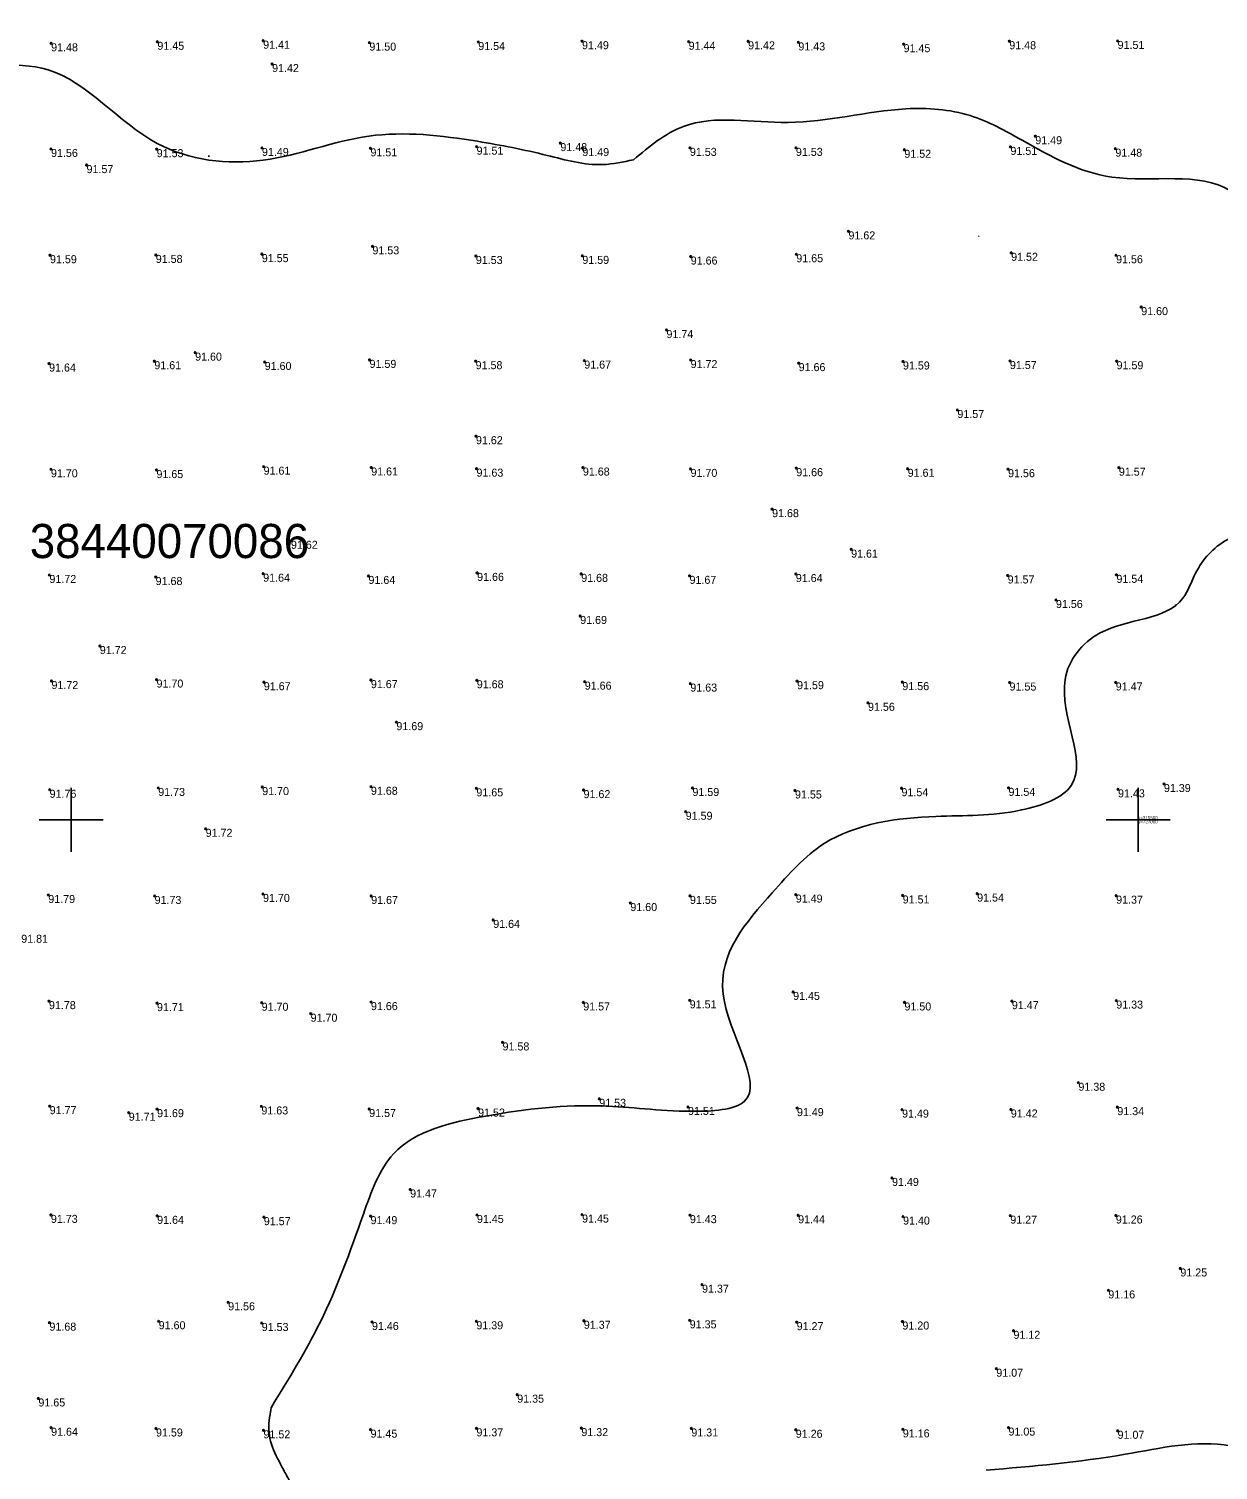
# Model space of a CAD drawing. Extents: x 316000 to 728450, y 314368 to 726000.
# Drawn here: x 726480 to 727038, y 315195 to 315871 of the extents above; entities that cross this region are included whole.
import ezdxf

# ---------------------------------------------------------------- set-up
doc = ezdxf.new("R2010")
doc.units = 0
for name, color, linetype in [('59', 7, 'Continuous'), ('GEOD_ELEM_####_####_#', 7, 'Continuous'), ('GEOD_KORD_####_TKST_#', 7, 'Continuous'), ('RELJ_AATZ_####_TKST_#', 7, 'Continuous'), ('RELJ_ELEM_####_####_#', 7, 'Continuous'), ('RELJ_HORZ_PAMT_####_#', 7, 'Continuous')]:
    doc.layers.add(name, color=color, linetype=linetype)

msp = doc.modelspace()

# ---------------------------------------------------------------- linework, layer by layer
at = {"layer": 'GEOD_ELEM_####_####_#'}
for p, q in [((726500, 315515), (726500, 315500)), ((727000, 315515), (727000, 315500)), ((726485, 315500), (726500, 315500)), ((726500, 315500), (726500, 315485)), ((726500, 315500), (726515, 315500)), ((726985, 315500), (727000, 315500)), ((727000, 315500), (727000, 315485)), ((727000, 315500), (727015, 315500))]:
    msp.add_line(p, q, dxfattribs=at)
at = {"layer": 'RELJ_ELEM_####_####_#'}
for centre in [(726490.67, 315863.76), (726540.47, 315864.48), (726590.02, 315864.97), (726639.81, 315864.09), (726690.82, 315864.36), (726739.45, 315864.76), (726789.42, 315864.5), (726817.28, 315864.7), (726840.82, 315864.18), (726890.11, 315863.35), (726939.66, 315864.74), (726990.41, 315864.88), (726594.22, 315854.05), (726951.84, 315820.25), (726490.64, 315814.28), (726540.15, 315814.17), (726589.46, 315814.74), (726640.3, 315814.55), (726690.03, 315815.34), (726729.3, 315817.01), (726739.58, 315814.68), (726789.99, 315814.78), (726839.67, 315814.78), (726890.48, 315813.88), (726940.2, 315815.25), (726989.37, 315814.41), (726507.27, 315806.7), (726864.29, 315775.65), (726490.15, 315764.49), (726539.71, 315764.63), (726589.39, 315765), (726641.23, 315768.66), (726689.69, 315764.12), (726739.59, 315764.18), (726839.86, 315764.94), (726940.52, 315765.61), (726989.7, 315764.47), (726790.38, 315763.86), (727001.47, 315740.16), (726779.01, 315729.41), (726558.15, 315718.83), (726489.72, 315713.73), (726539.04, 315714.82), (726590.75, 315714.48), (726639.88, 315715.45), (726689.59, 315714.84), (726740.5, 315715.11), (726790.33, 315715.36), (726840.95, 315713.92), (726889.82, 315714.69), (726939.94, 315714.9), (726989.92, 315714.82), (726915.34, 315691.97), (726689.75, 315679.69), (726490.57, 315664.17), (726540.03, 315663.82), (726590.23, 315665.42), (726640.66, 315665.03), (726690.01, 315664.48), (726739.85, 315665), (726790.29, 315664.37), (726839.82, 315664.71), (726892.05, 315664.43), (726939.09, 315664.24), (726991, 315664.94), (726828.52, 315645.51), (726603.04, 315630.7), (726865.58, 315626.64), (726690.29, 315615.66), (726489.87, 315614.68), (726539.64, 315613.7), (726590.04, 315615.27), (726639.37, 315614.23), (726739.06, 315615.19), (726789.81, 315614.27), (726839.63, 315615.11), (726938.9, 315614.44), (726989.86, 315614.74), (726961.52, 315602.95), (726738.59, 315595.48), (726513.48, 315581.38), (726490.83, 315564.98), (726540.07, 315565.67), (726590.33, 315564.43), (726640.51, 315565.41), (726690.13, 315565.35), (726740.72, 315564.7), (726790.2, 315563.79), (726840.23, 315564.92), (726889.54, 315564.48), (726939.78, 315564.28), (726989.54, 315564.32), (726873.46, 315554.78), (726652.46, 315545.72), (726540.86, 315514.9), (726589.58, 315515.3), (726640.53, 315515.45), (726689.94, 315514.7), (726791.18, 315514.87), (726889.15, 315514.77), (726939.27, 315514.94), (726990.6, 315514.22), (727012.11, 315516.73), (726489.95, 315514.04), (726740.16, 315513.88), (726839.23, 315513.71), (726788.03, 315503.74), (726563.09, 315495.75), (726489.34, 315464.73), (726539.15, 315464.29), (726589.97, 315465.25), (726640.64, 315464.28), (726762.08, 315460.96), (726790.02, 315464.32), (726839.61, 315464.94), (726889.7, 315464.53), (726924.6, 315465.4), (726989.73, 315464.41), (726697.83, 315453.07), (726489.65, 315415.01), (726540.27, 315414.08), (726589.32, 315414.26), (726640.54, 315414.56), (726740.01, 315414.39), (726789.91, 315415.38), (726838.36, 315419.33), (726890.53, 315414.39), (726940.85, 315415), (726989.77, 315415.27), (726612.26, 315409.11), (726702.19, 315395.67), (726972.05, 315376.77), (726489.99, 315365.81), (726589.2, 315365.68), (726747.51, 315369.24), (726527.05, 315362.73), (726540.33, 315364.4), (726639.71, 315364.46), (726690.75, 315364.69), (726789.11, 315365.44), (726840.14, 315364.9), (726889.41, 315364.2), (726940.37, 315364.25), (726990.28, 315365.35), (726884.71, 315332.19), (726658.9, 315326.77), (726490.56, 315314.87), (726540.36, 315314.42), (726590.33, 315313.8), (726640.35, 315314.28), (726690.2, 315314.84), (726739.47, 315315.01), (726789.99, 315314.74), (726840.72, 315314.68), (726889.88, 315314.07), (726940.12, 315314.51), (726989.57, 315314.58), (727019.82, 315289.77), (726795.69, 315282.16), (726986.06, 315279.48), (726573.64, 315273.91), (726489.89, 315264.38), (726541.08, 315265.04), (726641.01, 315264.68), (726689.93, 315265.03), (726740.29, 315265.26), (726789.91, 315265.47), (726840.02, 315264.61), (726889.58, 315264.9), (726589.36, 315264.22), (726941.62, 315260.56), (726933.57, 315242.79), (726709.07, 315230.63), (726484.72, 315228.86), (726490.67, 315215.13), (726539.82, 315214.8), (726590.18, 315213.92), (726640.35, 315214.24), (726689.97, 315214.87), (726739.13, 315214.97), (726790.67, 315214.81), (726839.6, 315214.19), (726889.76, 315214.37), (726939.27, 315215.21), (726990.39, 315213.72)]:
    msp.add_circle(centre, 0.375, dxfattribs=at)
at = {"layer": 'RELJ_HORZ_PAMT_####_#'}
for p, q in [((726564.59, 315811.13), (726564.5, 315810.64)), ((726925.57, 315773.53), (726925.22, 315773.18)), ((727017.9, 315600.38), (727017.61, 315600.79))]:
    msp.add_line(p, q, dxfattribs=at)
for points in [[(727407.26, 315826.81), (727420.88, 315859.78), (727421.31, 315861.98), (727420.84, 315873.16), (727415.63, 315882.87), (727395.8, 315899.43), (727371.45, 315914.61), (727360.58, 315922.6), (727355.76, 315932.78), (727350.87, 315945.8), (727343.65, 315965.03), (727334.62, 315981.5), (727324.71, 316005.53), (727317, 316014.24), (727310.95, 316025.93), (727306.22, 316036.97), (727300.2, 316049.01), (727293.8, 316067.18), (727252.55, 316104.18), (727204.11, 316093.45), (727172.31, 316071.99), (727104.82, 316081.23), (727087.15, 316092.31), (727070.62, 316103.93), (727040.63, 316117.26), (727014.6, 316106.53), (727006.58, 316100.22), (727000.85, 316096.21), (726994.11, 316090.82), (726983.98, 316084.66), (726972.39, 316080.59), (726966.37, 316079.01), (726958.49, 316076.14), (726948.07, 316071.06), (726932.7, 316067.7), (726916.22, 316058.14), (726880.98, 316039.68), (726836.99, 316020.53), (726807.52, 316005.55), (726787.17, 315993.15), (726764.31, 315989.32), (726742.06, 315986.79), (726725.03, 315990.27), (726708.15, 315999.77), (726691.28, 316009.5), (726674.31, 316013.66), (726659.02, 316010.43), (726643.66, 316003.77), (726628.26, 315996.72), (726612.85, 315992.34), (726600.2, 315993.32), (726587.04, 315996.97), (726574, 315999.47), (726567.72, 315999.1), (726561.71, 315997.03), (726548.35, 315992.52), (726536.61, 315988.25), (726525.25, 315984.49), (726513.03, 315977.96), (726485.95, 315966.35), (726456.08, 315949.13), (726439.28, 315937.58), (726388.53, 315922.53), (726290.27, 315916.68), (726240.08, 315917.6), (726226.6, 315921.61), (726211.69, 315923.04), (726191.22, 315924.62), (726136.88, 315919.22), (726111.29, 315920.51), (726086.94, 315922.23)], [(726763.5, 315809.19), (726749.16, 315806.95), (726723.09, 315811.25), (726690.49, 315817.84), (726639.53, 315820.26), (726590.09, 315809.02), (726540.4, 315816.89), (726489.33, 315851.36), (726436.89, 315851.36), (726370.59, 315850.01), (726333.14, 315821.86), (726290.46, 315814.62), (726273.5, 315803.45), (726235.67, 315774.14), (726190.27, 315750.2), (726153.69, 315699.03)], [(726593.88, 315224.8), (726616.82, 315264.75), (726637, 315315.27), (726651.14, 315343.51), (726694.36, 315361.19), (726749.01, 315365.93), (726790.76, 315363.41), (726815.6, 315368.11), (726805.57, 315418.29), (726828.59, 315465.79), (726852.93, 315488.83), (726905.28, 315501.59), (726945.42, 315504.58), (726968.66, 315516.03), (726965.81, 315565.73), (726982.16, 315587.51), (727021.03, 315603.83), (727026.91, 315615.45), (727041.79, 315631.21), (727064.99, 315643.98), (727068.28, 315660.17), (727074.4, 315715.03), (727062.43, 315768.22), (727043.33, 315794.59), (726987.68, 315801.12), (726945.68, 315818.33), (726921.32, 315829.91), (726891.24, 315833.06), (726835.97, 315826.66), (726786.96, 315824.85), (726763.5, 315809.19)], [(726928.87, 315195.26), (726993.94, 315202.7), (727043.38, 315206.65), (727070.97, 315200.67), (727099.07, 315208.23), (727115.13, 315218.79), (727163.97, 315245.43), (727197.67, 315261.25), (727223.74, 315268.27), (727261.86, 315293.04), (727271.52, 315318.75), (727275.31, 315365.73), (727304.87, 315408.07), (727318.25, 315430.8), (727296.61, 315466.6), (727280.52, 315513.02), (727314.54, 315556.78), (727346.44, 315559.08), (727353.49, 315563.23), (727377.71, 315615.11), (727387.39, 315664.9), (727376.7, 315713.43), (727392.03, 315764.86), (727407.26, 315826.81)], [(726590.47, 315064.89), (726602.04, 315086.78), (726604.87, 315092.38), (726607.33, 315098.19), (726609.11, 315104.19), (726609.9, 315110.33), (726610.11, 315122.37), (726610.15, 315134.42), (726610.15, 315152.2), (726610.04, 315157.61), (726609.74, 315163.01), (726609.27, 315168.41), (726608.65, 315173.81), (726605.29, 315184.9), (726603.89, 315187.59), (726602.43, 315190.24), (726600.97, 315192.87), (726599.55, 315195.53), (726594.39, 315206.11), (726592.95, 315211.53), (726592.75, 315217.1), (726593.5, 315222.69), (726593.88, 315224.8)]]:
    msp.add_spline(points, degree=3, dxfattribs=at)

# ---------------------------------------------------------------- texts
at = {"layer": '59'}
msp.add_text('38440070086', height=16, dxfattribs=at).set_placement((726480.65, 315622.58))
at = {"layer": 'GEOD_KORD_####_TKST_#'}
for s, p in [('x=315500', (727000, 315500.23)), ('y=727000', (727000, 315498.28))]:
    msp.add_text(s, height=1.5, dxfattribs=at).set_placement(p)
at = {"layer": 'RELJ_AATZ_####_TKST_#'}
for s, p in [('91.48', (726490.67, 315860.01)), ('91.45', (726540.47, 315860.73)), ('91.41', (726590.02, 315861.22)), ('91.50', (726639.81, 315860.34)), ('91.54', (726690.82, 315860.61)), ('91.49', (726739.45, 315861.01)), ('91.44', (726789.42, 315860.75)), ('91.42', (726817.28, 315860.95)), ('91.43', (726840.82, 315860.43)), ('91.45', (726890.11, 315859.6)), ('91.48', (726939.66, 315860.99)), ('91.51', (726990.41, 315861.13)), ('91.42', (726594.22, 315850.3)), ('91.49', (726951.84, 315816.5)), ('91.56', (726490.64, 315810.53)), ('91.53', (726540.15, 315810.42)), ('91.49', (726589.46, 315810.99)), ('91.51', (726640.3, 315810.8)), ('91.51', (726690.03, 315811.59)), ('91.48', (726729.3, 315813.26)), ('91.49', (726739.58, 315810.93)), ('91.53', (726789.99, 315811.03)), ('91.53', (726839.67, 315811.03)), ('91.52', (726890.48, 315810.13)), ('91.51', (726940.2, 315811.5)), ('91.48', (726989.37, 315810.66)), ('91.57', (726507.27, 315802.95)), ('91.62', (726864.29, 315771.9)), ('91.59', (726490.15, 315760.74)), ('91.58', (726539.71, 315760.88)), ('91.55', (726589.39, 315761.25)), ('91.53', (726641.23, 315764.91)), ('91.65', (726839.86, 315761.19)), ('91.52', (726940.52, 315761.86)), ('91.56', (726989.7, 315760.72)), ('91.53', (726689.69, 315760.37)), ('91.59', (726739.59, 315760.43)), ('91.66', (726790.38, 315760.11)), ('91.60', (727001.47, 315736.41)), ('91.74', (726779.01, 315725.66)), ('91.60', (726558.15, 315715.08)), ('91.64', (726489.72, 315709.98)), ('91.61', (726539.04, 315711.07)), ('91.60', (726590.75, 315710.73)), ('91.59', (726639.88, 315711.7)), ('91.58', (726689.59, 315711.09)), ('91.67', (726740.5, 315711.36)), ('91.72', (726790.33, 315711.61)), ('91.66', (726840.95, 315710.17)), ('91.59', (726889.82, 315710.94)), ('91.57', (726939.94, 315711.15)), ('91.59', (726989.92, 315711.07)), ('91.57', (726915.34, 315688.22)), ('91.62', (726689.75, 315675.94)), ('91.70', (726490.57, 315660.42)), ('91.65', (726540.03, 315660.07)), ('91.61', (726590.23, 315661.67)), ('91.61', (726640.66, 315661.28)), ('91.63', (726690.01, 315660.73)), ('91.68', (726739.85, 315661.25)), ('91.70', (726790.29, 315660.62)), ('91.66', (726839.82, 315660.96)), ('91.61', (726892.05, 315660.68)), ('91.56', (726939.09, 315660.49)), ('91.57', (726991, 315661.19)), ('91.68', (726828.52, 315641.76)), ('91.62', (726603.04, 315626.95)), ('91.61', (726865.54, 315622.8)), ('91.72', (726489.87, 315610.93)), ('91.68', (726539.64, 315609.95)), ('91.64', (726590.04, 315611.52)), ('91.64', (726639.37, 315610.48)), ('91.66', (726690.29, 315611.91)), ('91.68', (726739.06, 315611.44)), ('91.67', (726789.81, 315610.52)), ('91.64', (726839.63, 315611.36)), ('91.57', (726938.9, 315610.69)), ('91.54', (726989.86, 315610.99)), ('91.56', (726961.52, 315599.2)), ('91.69', (726738.59, 315591.73)), ('91.72', (726513.48, 315577.63)), ('91.72', (726490.83, 315561.23)), ('91.70', (726540.07, 315561.92)), ('91.67', (726590.33, 315560.68)), ('91.67', (726640.51, 315561.66)), ('91.68', (726690.13, 315561.6)), ('91.66', (726740.72, 315560.95)), ('91.63', (726790.2, 315560.04)), ('91.59', (726840.23, 315561.17)), ('91.56', (726889.54, 315560.73)), ('91.55', (726939.78, 315560.53)), ('91.47', (726989.54, 315560.57)), ('91.56', (726873.46, 315551.03)), ('91.69', (726652.46, 315541.97)), ('91.73', (726540.86, 315511.15)), ('91.70', (726589.58, 315511.55)), ('91.68', (726640.53, 315511.7)), ('91.65', (726689.94, 315510.95)), ('91.59', (726791.18, 315511.12)), ('91.54', (726889.15, 315511.02)), ('91.54', (726939.27, 315511.19)), ('91.39', (727012.11, 315512.98)), ('91.76', (726489.95, 315510.29)), ('91.62', (726740.16, 315510.12)), ('91.55', (726839.23, 315509.96)), ('91.43', (726990.6, 315510.47)), ('91.59', (726788.03, 315499.99)), ('91.72', (726563.09, 315492)), ('91.79', (726489.34, 315460.98)), ('91.73', (726539.15, 315460.54)), ('91.70', (726589.97, 315461.5)), ('91.67', (726640.64, 315460.53)), ('91.60', (726762.08, 315457.21)), ('91.55', (726790.02, 315460.57)), ('91.49', (726839.61, 315461.19)), ('91.51', (726889.7, 315460.78)), ('91.54', (726924.6, 315461.65)), ('91.37', (726989.73, 315460.66)), ('91.64', (726697.83, 315449.32)), ('91.81', (726476.66, 315442.36)), ('91.78', (726489.65, 315411.26)), ('91.71', (726540.27, 315410.33)), ('91.70', (726589.32, 315410.51)), ('91.66', (726640.54, 315410.81)), ('91.57', (726740.01, 315410.64)), ('91.51', (726789.91, 315411.63)), ('91.45', (726838.36, 315415.58)), ('91.50', (726890.53, 315410.64)), ('91.47', (726940.85, 315411.25)), ('91.33', (726989.77, 315411.52)), ('91.70', (726612.26, 315405.36)), ('91.58', (726702.2, 315391.92)), ('91.38', (726972.05, 315373.02)), ('91.53', (726747.51, 315365.49)), ('91.77', (726489.99, 315362.06)), ('91.71', (726527.05, 315358.98)), ('91.69', (726540.33, 315360.65)), ('91.63', (726589.2, 315361.93)), ('91.57', (726639.71, 315360.71)), ('91.52', (726690.75, 315360.94)), ('91.51', (726789.11, 315361.69)), ('91.49', (726840.14, 315361.15)), ('91.49', (726889.41, 315360.45)), ('91.42', (726940.37, 315360.5)), ('91.34', (726990.28, 315361.6)), ('91.49', (726884.71, 315328.44)), ('91.47', (726658.9, 315323.02)), ('91.73', (726490.56, 315311.12)), ('91.64', (726540.36, 315310.67)), ('91.57', (726590.33, 315310.05)), ('91.49', (726640.35, 315310.53)), ('91.45', (726690.2, 315311.09)), ('91.45', (726739.47, 315311.26)), ('91.43', (726789.99, 315310.99)), ('91.44', (726840.72, 315310.93)), ('91.40', (726889.88, 315310.32)), ('91.27', (726940.12, 315310.76)), ('91.26', (726989.57, 315310.83)), ('91.25', (727019.82, 315286.02)), ('91.37', (726795.69, 315278.41)), ('91.16', (726986.06, 315275.73)), ('91.56', (726573.64, 315270.16)), ('91.60', (726541.08, 315261.29)), ('91.46', (726641.01, 315260.93)), ('91.39', (726689.93, 315261.28)), ('91.37', (726740.29, 315261.51)), ('91.35', (726789.91, 315261.72)), ('91.27', (726840.02, 315260.86)), ('91.20', (726889.58, 315261.15)), ('91.68', (726489.89, 315260.63)), ('91.53', (726589.36, 315260.47)), ('91.12', (726941.61, 315256.81)), ('91.07', (726933.57, 315239.04)), ('91.65', (726484.72, 315225.11)), ('91.35', (726709.07, 315226.88)), ('91.64', (726490.67, 315211.38)), ('91.59', (726539.82, 315211.05)), ('91.52', (726590.18, 315210.17)), ('91.45', (726640.35, 315210.49)), ('91.37', (726689.97, 315211.12)), ('91.32', (726739.13, 315211.22)), ('91.31', (726790.67, 315211.06)), ('91.26', (726839.6, 315210.44)), ('91.16', (726889.76, 315210.62)), ('91.05', (726939.27, 315211.46)), ('91.07', (726990.39, 315209.97))]:
    msp.add_text(s, height=3.75, dxfattribs=at).set_placement(p)

doc.saveas('drawing.dxf')
